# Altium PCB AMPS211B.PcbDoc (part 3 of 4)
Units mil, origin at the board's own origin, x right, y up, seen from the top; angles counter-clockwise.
Board outline 3600 x 2600 mil, 4 copper layers (Top Layer, GND, Power, Bottom Layer), stack 61.6 mil thick; 202 components, 101 nets, 561 pads, 317 vias.
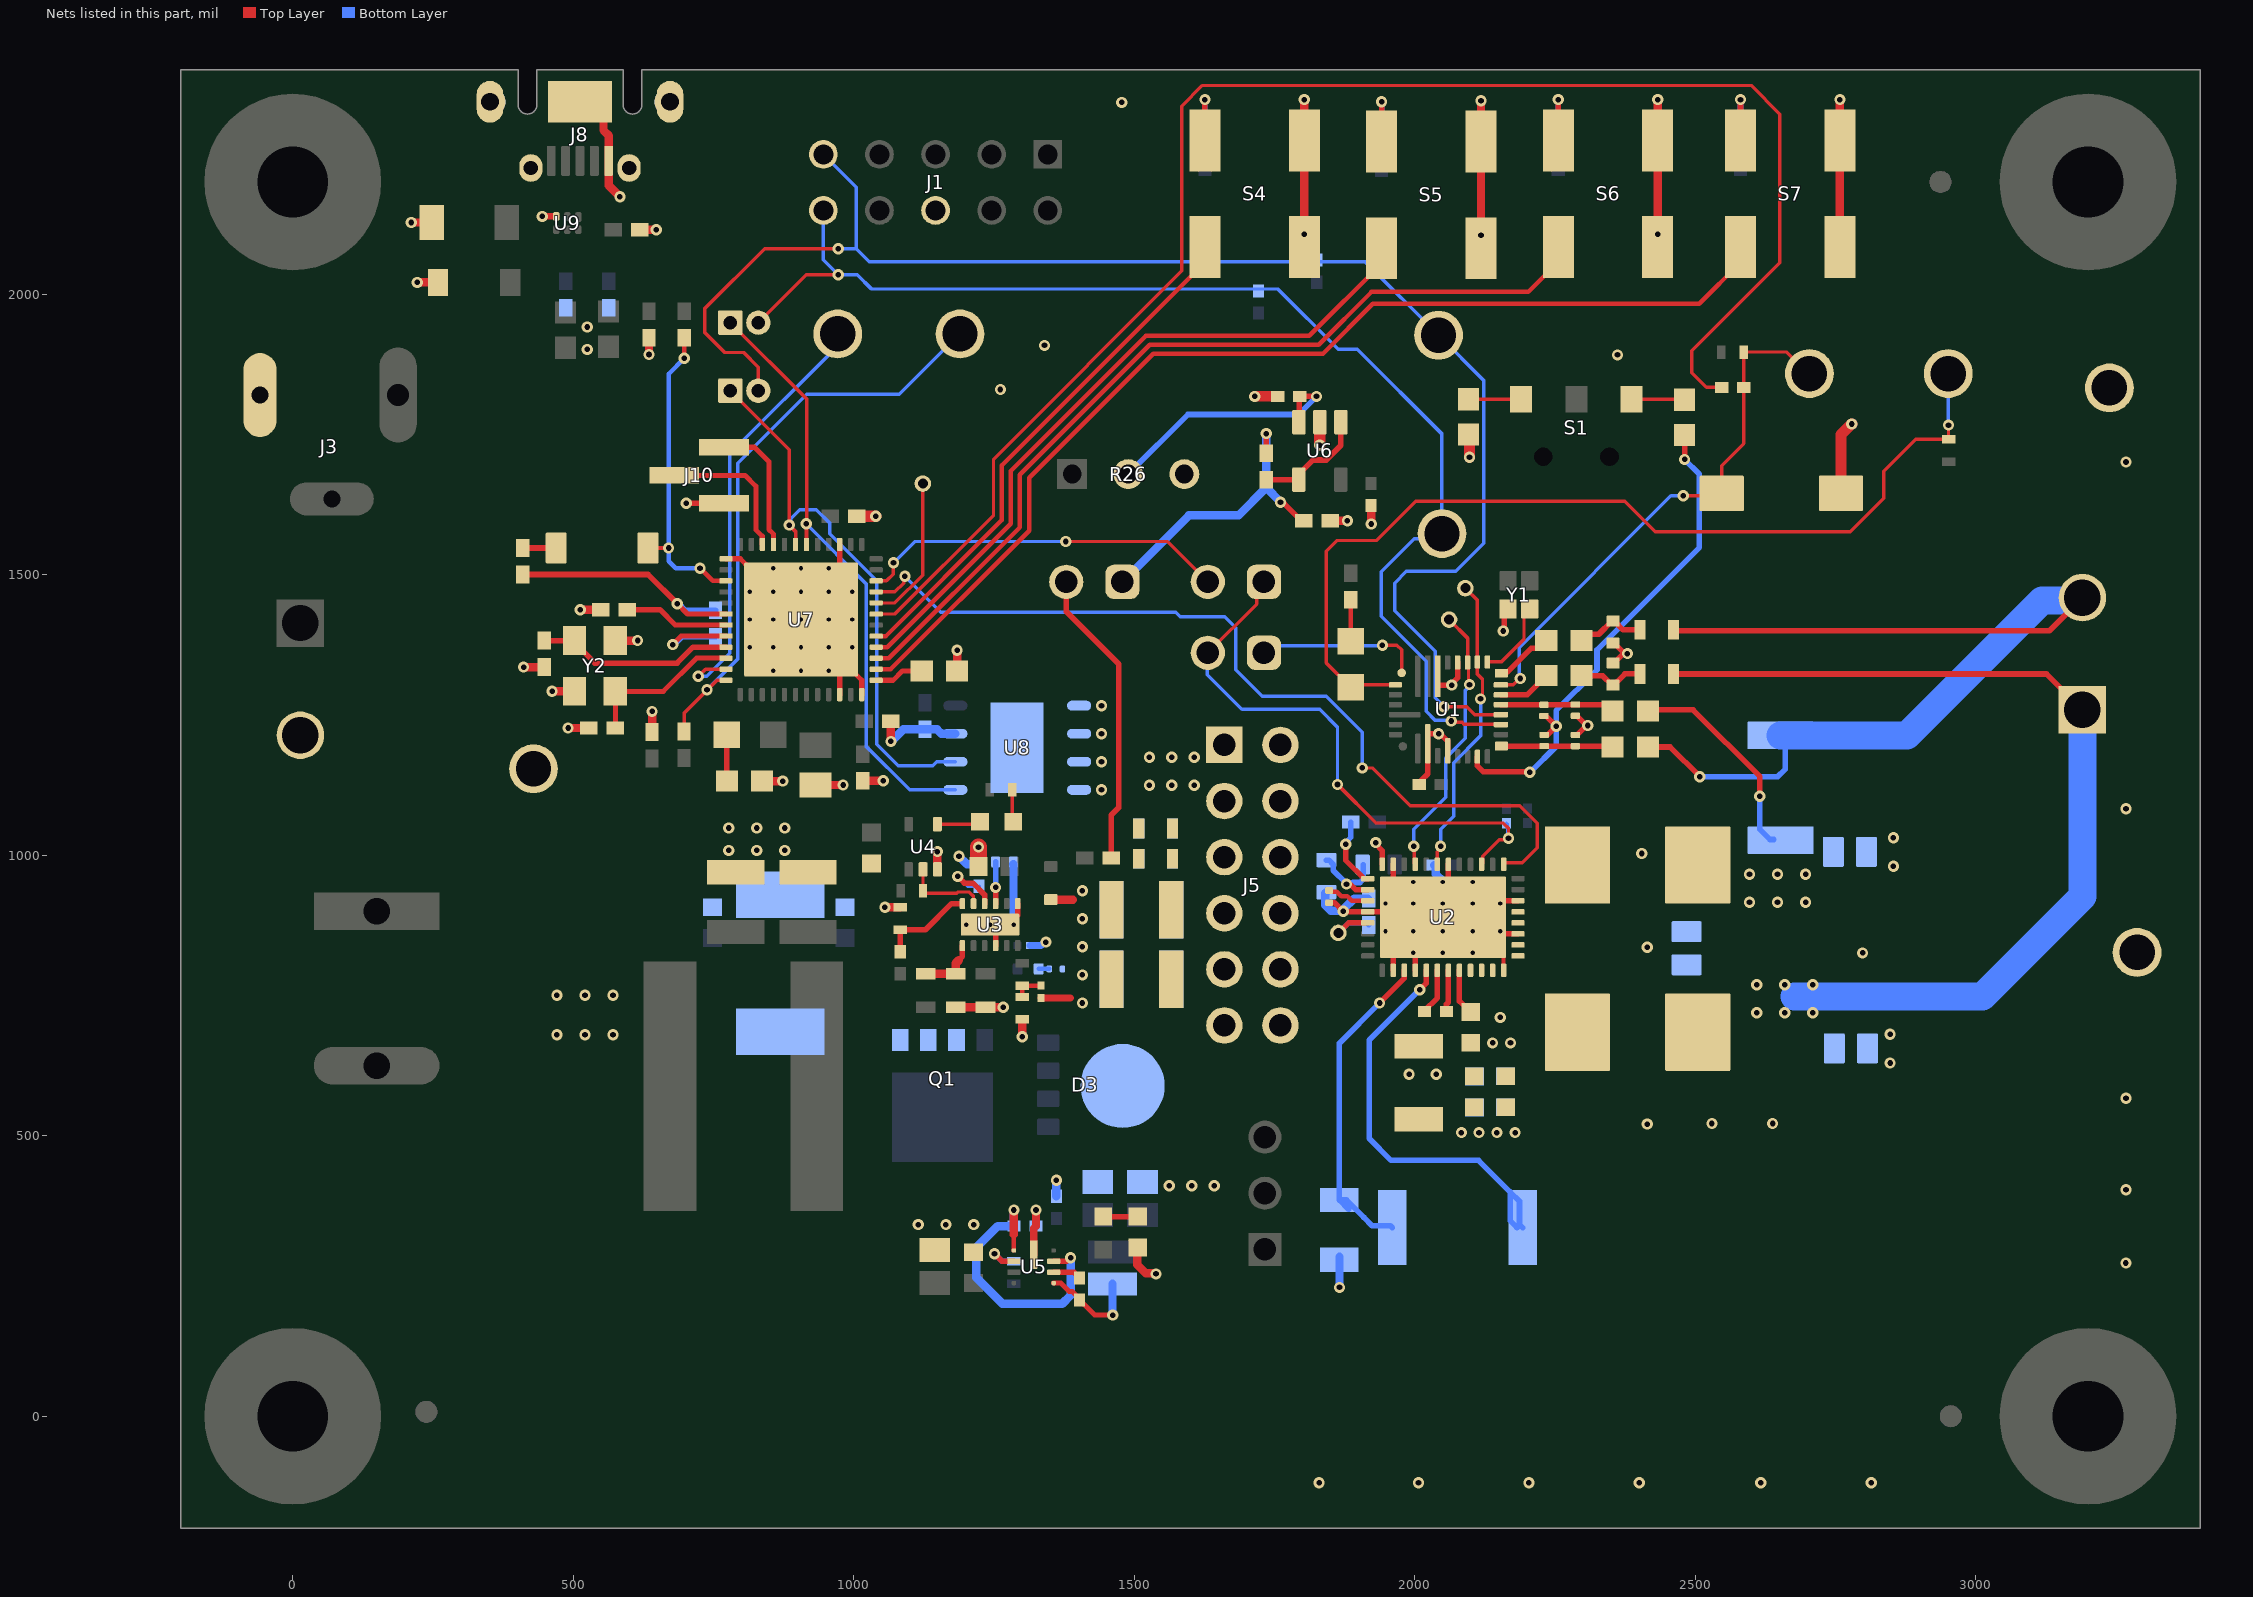
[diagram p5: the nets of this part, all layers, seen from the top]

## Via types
v1: diameter 20, hole 10, Top Layer to Bottom Layer, tented both sides, 277 vias
v2: diameter 19.68, hole 7.87, Top Layer to Bottom Layer, 24 vias
v3: diameter 19.68, hole 7.87, Top Layer to Bottom Layer, tented both sides, 16 vias

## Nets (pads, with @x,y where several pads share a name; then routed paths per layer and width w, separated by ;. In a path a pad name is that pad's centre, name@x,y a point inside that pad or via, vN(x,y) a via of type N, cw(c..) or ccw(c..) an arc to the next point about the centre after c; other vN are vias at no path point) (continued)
GND: C1.2 C3.2 C4.2 C5.2 C7.2 C8.2 C37.2 C38.2 C39.2 C40.1 C41.1 C42.2 C43.2 C44.2 C45.2 C46.2 C47.2 C48.2 C49.2 C50.2 C51.2 C52.2 C53.2 C54.2 C55.2 C56.1 D5.2 J1.6 J5.2 J5.4 J5.6 J8.5 J8.6 J8.7 J8.8 J8.9 J8.10 J10.3 R7.1 R10.1 R15.1 R19.1 R25.1 R42.1 R52.1 R54.1 R57.1 S2.1 S4.3 S4.4 S5.3 S5.4 S6.3 S6.4 S7.3 S7.4 TP2.1 TP3.1 U1.12 U1.14 U1.26 U1.28 U2.2 U2.4 U2.12 U2.15 U2.18 U2.26 U2.31 U2.32 U2.36 U2.41 U7.10 U7.12 U7.27 U7.37 U7.44 U7.49 U8.1 U8.2 U8.3 U8.4 U8.7 U8.9 U9.3 Y1.2 Y2.2 Y2.4 | length 3877.4
  Top Layer w7.5: U2.12@2158.32,794.78 U2.41@2158.32,824.5
  Top Layer w8: U2.41@2147.87,834.95 U2.41@2158.32,824.5
  Top Layer w9.4: v1(677.31,1375.29) 692.5,1390.51 U7.44@772.13,1390.51 ; U7.37@772.13,1528.31 797.74,1528.29 814.45,1511.58 v2(814.45,1469.65) ; v2(905.99,1420.04) v2(955.59,1370.44) 1014.25,1311.77 U7.12@1014.25,1286.18 ; v2(955.59,1328.51) 969.94,1328.51 974.88,1323.56 U7.10@974.88,1286.18 ; v2(955.59,1511.58) 969.94,1511.58 974.88,1516.52 U7.27@974.88,1553.9
  Top Layer w9.5: v1(1930.42,1022.45) 1930.42,1019.61 1941.77,1008.26 U2.32@1941.77,983.88 ; U2.2@1961.47,794.78 U2.41@1961.47,828.56 ; U2.41@1961.47,951 U2.31@1961.47,983.76 ; U2.4@2000.84,794.78 U2.41@2000.84,828.56 ; U2.41@2059.89,949.98 U2.26@2059.89,983.76 ; U2.41@2150.13,859.74 U2.15@2183.91,859.74 ; U2.41@2150.13,918.79 U2.18@2183.91,918.79
  Top Layer w9.8: v1(701.39,1627.37) 768.56,1627.37 J10.3@768.79,1627.14 ; R57.1@1847.24,915.35 1856.64,915.35 1871.96,900.04 v1(1872.34,900.04) 1873.25,899.13 U2.36@1916.17,899.13 ; U2.36@1916.19,899.11 2040.21,899.11 U2.41@2050.05,889.27 ; C5.2@2011.81,1133.86 2023.06,1145.11 U1.26@2023.08,1198.44 ; U1.26@2023.08,1198.44 2023.08,1216.51 2041.34,1216.54 2043.29,1214.58 2047.69,1214.58 2058.51,1203.76 U1.28@2058.51,1186.04 ; U1.14@2040.77,1303.68 2040.77,1303.19 2040.82,1303.15 v1(2065.94,1303.15) 2065.94,1305.74 2076.23,1316.03 U1.12@2076.23,1343.52 ; v1(2157.48,1399.61) 2159.43,1401.56 2159.43,1436.01 Y1.2@2160.43,1437.01 ; R15.1@2286.33,1214.4 2289.28,1214.4 2306.17,1231.3 v1@2306.37,1231.3 ; R10.1@2286.33,1248.39 2289.28,1248.39 v1@2306.37,1231.3 ; v1@2309.06,1231.3 v1@2306.37,1231.3 ; R25.1@2353.35,1342.52 2355.32,1342.52 v1@2372.05,1359.25 ; R19.1@2353.35,1377.95 2355.32,1377.95 2374.02,1359.25 v1(2378.94,1359.25)
  Top Layer w11.8: v1(444.78,2138.53) U9.3@469.68,2138.53
  Top Layer w15: v1(211.17,2127.7) C44.2@247.84,2127.7 ; v1(222.1,2020.98) D5.2@258.76,2020.98 ; v1(411.43,1335.32) C40.1@448.24,1335.32 ; v1(462.28,1292.02) Y2.4@502.09,1292.02 ; v1(490.87,1226.63) C41.1@527.68,1226.63 ; J8.9@512.01,2342.91 523.99,2342.91 553.89,2313.01 553.89,2291.8 563.19,2282.5 J8.5@563.19,2237.6 563.19,2193.62 v1(583.16,2173.65) ; v1(512.33,1437.6) C47.2@549.14,1437.6 ; Y2.2@574.92,1382.57 v1(614.73,1382.57) ; C46.2@618.29,2114.91 v1(647.95,2114.91) ; v1(635.04,1892.38) R52.1@635.04,1922.05 ; C50.2@640.51,1219.55 v1(640.51,1256.36) ; R54.1@836.69,1132 v1(873.5,1132) ; C51.2@932.17,1125.15 v1(980.98,1125.15) ; C53.2@1015.85,1132.87 v1(1052.67,1132.87) ; v1(1066.1,1202.85) C54.2@1066.1,1238.83 C54.2@1066.1,1239.67 ; C48.2@1184.15,1328.51 v1(1184.15,1365.32) ; S4.4@1803.02,2083.96 S4.3@1803.02,2273.92 v1(1803.02,2346.8) ; S5.4@2117.98,2081.99 S5.3@2117.98,2271.95 v1(2117.98,2344.83) ; S6.4@2432.94,2083.96 S6.3@2432.94,2273.92 v1(2432.94,2346.8) ; S7.4@2757.74,2083.96 S7.3@2757.74,2273.92 v1(2757.74,2346.8)
  Top Layer w20: C52.2@1005.36,1604.29 v1(1039.17,1604.29) ; v1(2097.56,1709.1) R7.1@2097.56,1746.78 ; S2.1@2759.62,1644.88 2759.62,1749.49 v1(2778.71,1768.58)
  Bottom Layer w9.8: v1(677.31,1375.29) 680.07,1375.29 693.83,1389.05 C49.2@753.58,1389.05
  Bottom Layer w15: v1@1066.74,1202.85 1088.44,1224.55 C45.2@1126.9,1224.55 ; C45.2@1132.31,1224.14 1148.46,1224.14 1156.11,1216.49 U8.7@1181.13,1216.49 ; R42.1@1842.33,934.15 1840.3,932.13 1840.3,911.09 1850.41,900.99 1871.39,900.99 v1(1872.34,900.04) ; v1(1865.74,229.64) C8.2@1865.74,284.45 ; v1@1872.34,903.04 1892.04,922.73 C7.2@1916.07,922.73 ; C1.2@2034.45,982.28 2035.25,982.28 2037.13,980.4 2037.13,966.44 2050.05,953.53 v3(2050.05,952.26)
  other v1: 1829.33,-118.78 2006.49,-118.78 2203.34,-118.78 2400.19,-118.78 2616.73,-118.78 2813.58,-118.78 3267.46,273.08 3267.67,403.53 2082.98,505.53 2114.43,505.53 2146.36,505.53 2178.67,505.53 2414.28,520.76 2529.53,521.65 2637.8,521.65 3267.72,566.93 2847.12,629.5 2847.12,680.96 2798.14,825.87 2414.28,835.72 2853,980.21 2404.44,1003.04 2853,1031.01 3267.72,1082.68 1441.6,1116.49 1441.6,1166.49 1441.6,1216.49 2042.32,1216.54 2308.33,1231.25 1441.6,1266.49 3267.72,1700.79 1261.28,1829.97 2361.22,1891.73 524.8,1901.45 1340.02,1908.71 524.8,1941.45 2117.98,2104.67 1803.02,2106.64 2432.94,2106.64 1477.81,2341.78
  other v2: 856.38,1328.51 905.99,1328.51 814.45,1370.44 856.38,1370.44 905.99,1370.44 997.52,1370.44 814.45,1420.04 856.38,1420.04 955.59,1420.04 997.52,1420.04 856.38,1469.65 905.99,1469.65 955.59,1469.65 997.52,1469.65 856.38,1511.58 905.99,1511.58
  other v3: 1996.9,826.27 2050.05,826.27 2103.2,826.27 1947.69,864.66 1996.9,864.66 2050.05,864.66 2103.2,864.66 2152.41,864.66 1947.69,913.87 1996.9,913.87 2050.05,913.87 2103.2,913.87 2152.41,913.87 1996.9,952.26 2103.2,952.26
INCLK: U1.9 Y1.3 | length 132.4
  Top Layer w6.2: U1.9@2129.38,1344.51 2154.54,1344.51 2194.63,1384.59 2194.63,1434.79 Y1.3@2194.88,1435.04
IRQZ: D2.2 R21.2 TP12.1 U1.18 | length 1723.1
  Top Layer w6: U1.18@1965.4,1303.64 1890.3,1303.64 D2.2@1885.73,1299.07 1842.26,1342.54 1842.26,1541.54 1861.68,1560.95 1931.83,1560.95 2001.89,1631.01 2374.39,1631.01 2428.82,1576.58 2776.46,1576.58 2835.99,1636.12 2835.99,1684.45 2892.65,1741.11 R21.2@2951.35,1741.11 v1(2951.35,1766.61)
  Bottom Layer w6: TP12.1@2950.7,1855.47 2950.7,1765.96 v1(2951.35,1766.61)
ISNS_N: R8.1 R9.1 R10.2 U1.5 | length 209.5
  Top Layer w9.8: U1.5@2153.39,1268.21 R8.1@2230.11,1268.21 2255.7,1268.21 ; 2255.83,1268.34 2286.33,1268.34 2315.72,1268.34 ; 2315.98,1268.34 R9.1@2363.33,1268.34
ISNS_P: R13.1 R14.1 R15.2 U1.1 | length 208.9
  Top Layer w9.8: U1.1@2154.41,1194.36 2256.25,1194.36 ; 2256.27,1194.34 2315.84,1194.34 ; 2315.92,1194.4 R14.1@2363.39,1194.4
MSP430_SDZ: R22.2 U7.19 | length 2842.8
  Top Layer w6: U7.19@1039.84,1429.88 1073.23,1429.88 1249.14,1605.79 1249.14,1706 1584.52,2041.38 1584.52,2334.98 1621.54,2372 2599.38,2372 2650.7,2320.68 2650.7,2056.05 2493.81,1899.15 2493.81,1859.91 2519.85,1833.86 R22.2@2547.03,1833.86
NetC2_2: C2.2 U2.8 | length 83.1
  Top Layer w9.8: U2.8@2079.58,794.78 2079.58,739.7 2098.72,720.55 C2.2@2099.7,720.55
NetC6_1: C6.1 U2.6 | length 82.5
  Top Layer w9.4: C6.1@2016.69,721.97 2040.21,745.49 U2.6@2040.21,794.78
NetC6_2: C6.2 U2.7 | length 74.5
  Top Layer w9.8: C6.2@2056.16,721.87 2056.16,734.01 2059.89,737.74 U2.7@2059.89,794.78
NetC8_1: C8.1 R5.2 U2.3 | length 595.7
  Top Layer w9.8: v1(1937.16,736.61) 1981.07,780.52 U2.3@1981.07,794.7
  Bottom Layer w10: C8.1@1882.08,368.8 C8.1@1865.43,385.45 ; v1(1937.16,736.61) 1865.43,664.88 C8.1@1865.43,385.45 ; R5.2@1959.85,336.27 1956.65,339.47 1923.88,339.47 1909.38,353.97 1909.38,354.3 1878.22,385.45 C8.1@1865.43,385.45
NetC11_1: C11.1 U5.6 | length 50.5
  Top Layer w9.84: U5.6@1356.24,256.55 1392.58,256.55 C11.1@1402.58,246.55
NetC11_2: C11.2 L4.1 U5.5 | length 186.3
  Top Layer w9: U5.5@1356.24,237.34 1368.92,237.34 1383.89,222.37 1389.37,222.37 1402.58,209.15 C11.2@1402.58,207.18 1402.58,205.21 1407.93,199.87 1409.89,199.87 1429.47,180.3 v1(1461.5,180.3)
  Bottom Layer w15: v1@1461.11,180.69 L4.1@1461.11,235.75
NetC14_1: C14.1 C56.2 L2.2 R4.1 R9.2 | length 373.8
  Top Layer w10: R9.2@2417,1259 2496,1259 2615.09,1139.91 2615.09,1105.09 v1(2615,1105)
  Bottom Layer w10: v1(2615,1105) 2615,1046.1 2633.1,1028 R4.1@2640,1028
  other v1: 2596.48,916.03 2646.48,916.03 2696.48,916.03 2596.48,966.03 2646.48,966.03 2696.48,966.03
NetC16_1: C16.1 U5.1 U5.7 | length 530.5
  Top Layer w7.8: U5.1@1285.37,295.45 1285.37,323.97
  Top Layer w9: U5.7@1356.24,276.24 1380.38,276.24 v1(1386.42,282.27)
  Top Layer w15: 1285.37,323.97 v1(1285.37,367.6)
  Bottom Layer w15: v1(1285.37,367.6) C16.1@1285.37,338.76 1256.59,338.76 1218.33,300.49 1218.33,247.08 1264.95,200.46 1371.6,200.46 1386.42,215.28 v1(1386.42,282.27)
NetC18_1: C18.1 R26.2 U6.3 | length 467.6
  Top Layer w10: U6.3@1793.27,1771.77 1794.16,1772.66 1794.16,1816.88 C18.1@1795.04,1817.76 ; C18.1@1797.01,1817.76 v1(1824.85,1817.76)
  Bottom Layer w10: R26.2@1489.23,1679.28 1595.46,1785.51 1792.6,1785.51 v1(1824.85,1817.76)
NetC22_1: C22.1 R30.1 U3.1 | length 108.4
  Top Layer w9.8: 1187.02,812.71 1193.72,819.42 U3.1@1193.72,838.83
  Top Layer w15: R30.1@1128.28,788.83 C22.1@1181.72,788.83 1181.72,807.42 1187.02,812.71
NetC32_1: C32.1 R33.2 R34.1 | length 53.4
  Top Layer w8: R34.1@1300.46,747.29 R33.2@1300.46,767.33 C32.1@1333.79,767.33
NetC33_1: C33.1 R40.2 | length 18.8
  Bottom Layer w8: C33.1@1329.55,797.23 R40.2@1348.36,797.23
NetC36_1: C36.1 J11.1 R44.1 | length 549
  Top Layer w10: R44.1@1735.22,1716.65 v1(1735.22,1751.46) ; v1(1760.52,1628.94) 1762.43,1627.02 1766.84,1627.02 1797.91,1595.96 C36.1@1801.85,1595.96
  Bottom Layer w15: J11.1@1478.74,1487.2 1597.33,1605.79 1685.91,1605.79 1735.22,1655.11 ; v1(1735.22,1751.46) 1735.22,1655.11 ; v1@1760.83,1628.94 1760.83,1629.5 1735.22,1655.11
NetC40_2: C40.2 U7.45 Y2.3 | length 352.5
  Top Layer w9.4: 731.93,1370.83 U7.45@772.13,1370.83
  Top Layer w9.8: C40.2@448.24,1382.57 498.04,1382.57 538.45,1342.16 685.14,1342.16 713.81,1370.83 731.93,1370.83
NetC41_2: C41.2 U7.46 Y2.1 | length 287.1
  Top Layer w9: C41.2@574.92,1226.63 Y2.1@574.92,1292.02 660.49,1292.02 719.62,1351.14 U7.46@772.13,1351.14
NetC47_1: C47.1 U7.43 | length 187.1
  Top Layer w9.4: C47.1@596.38,1437.6 654.31,1437.6 681.71,1410.2 U7.43@772.13,1410.2
NetC48_1: C48.1 U7.13 | length 83.2
  Top Layer w9: U7.13@1039.84,1311.77 1070.11,1311.77 1086.84,1328.51 C48.1@1116.16,1328.51
NetD1_2: D1.2 R11.2 | length 61.3
  Top Layer w9.84: D1.2@1444.91,355.96 R11.2@1506.16,355.96
NetD2_1: D2.1 R27.2 | length 73.5
  Top Layer w8: D2.1@1885.73,1381.75 R27.2@1885.73,1455.23
NetD4_1: D4.1 R36.2 | length 55.2
  Top Layer w6: D4.1@1282.15,1061.4 R36.2@1282.15,1116.55
NetD4_2: D4.2 U4.4 | length 77.7
  Top Layer w6: U4.4@1149.02,1055.36 1221.01,1055.36 D4.2@1225.07,1059.42
NetD6_2: D6.2 R54.2 | length 82.7
  Top Layer w10: R54.2@773.69,1132 D6.2@773.69,1214.68
NetJ10_1: J10.1 U7.33 | length 241.5
  Top Layer w9: J10.1@768.79,1727.14 823.03,1727.14 848.57,1701.59 848.57,1580.7 856.55,1572.72 856.55,1554.12 U7.33@856.77,1553.9
NetJ10_2: J10.2 U7.34 | length 262
  Top Layer w9: J10.2@680.21,1677.14 799.09,1677.14 806.08,1677.14 825.46,1657.76 825.46,1579.95 836.86,1568.55 836.86,1554.12 U7.34@837.09,1553.9
NetJ11_2: J11.2 R28.2 | length 536.7
  Top Layer w10: J11.2@1378.94,1487.2 1378.74,1487.01 1378.74,1434.12 1472.31,1340.55 1472.31,1084.75 1458.69,1071.13 R28.2@1458.69,995.01
NetR5_1: R5.1 U2.5 | length 774
  Top Layer w9.4: v1@2008.88,760.3 2020.52,771.94 U2.5@2020.52,794.78
  Bottom Layer w10: v1(2008.75,760.3) 1918.69,670.24 1918.69,495.08 1957.85,455.92 2113.82,455.92 R5.1@2169.83,399.92 ; R5.1@2182.13,336.27 2169.83,348.58 R5.1@2169.83,399.92 ; R5.1@2192.13,336.27 2186.62,341.79 2186.62,383.12 R5.1@2169.83,399.92
NetR6_2: R6.2 S1.3 | length 95
  Top Layer w6: S1.3@2386.33,1812.73 2479.98,1812.73 R6.2@2480.93,1811.78
NetR7_2: R7.2 S1.1 | length 93.9
  Top Layer w6: R7.2@2095.56,1812.73 S1.1@2189.48,1812.73
NetR17_2: R17.2 R18.1 R19.2 | length 123.1
  Top Layer w10: R17.2@2296.26,1382.87 R17.2@2297.24,1382.87 R17.2@2309.55,1395.18 ; R17.2@2311.02,1393.7 2327.76,1393.7 R19.2@2351.38,1417.32 ; R19.2@2356,1416 2356.64,1416 2371.06,1401.57 R18.1@2404.56,1401.57
NetR23_2: R23.2 R24.1 R25.2 | length 115.2
  Top Layer w10: R23.2@2297.24,1319.88 2334.65,1319.88 R25.2@2350.39,1304.13 ; R25.2@2354.33,1303.15 2355.31,1303.15 2360.16,1307.99 2360.16,1308.98 2374.45,1323.26 R24.1@2400.94,1323.26
NetR44_2: R44.2 U6.1 U6.4 | length 205.2
  Top Layer w10: R44.2@1735.22,1669.41 U6.4@1793.27,1669.41 1793.27,1679.25 1818.51,1704.49 1842.06,1704.49 1868.07,1730.5 U6.1@1868.07,1771.77
NetR45_1: R45.1 S4.1 | length 145.8
  Top Layer w10: S4.1@1625.85,2273.92 v1(1625.85,2346.8)
  Bottom Layer w10: R45.1@1625.85,2273.92 v1(1625.85,2346.8)
NetR46_1: R46.1 S5.1 | length 145.8
  Top Layer w10: S5.1@1940.82,2269.98 v1(1940.82,2342.86)
  Bottom Layer w10: R46.1@1940.82,2269.98 v1(1940.82,2342.86)
NetR47_1: R47.1 S6.1 | length 145.8
  Top Layer w10: S6.1@2255.78,2273.92 v1(2255.78,2346.8)
  Bottom Layer w10: R47.1@2255.78,2273.92 v1(2255.78,2346.8)
NetR48_1: R48.1 S7.1 | length 145.8
  Top Layer w10: S7.1@2580.58,2273.92 v1(2580.58,2346.8)
  Bottom Layer w10: R48.1@2580.58,2273.92 v1(2580.58,2346.8)
NetR53_1: R53.1 S8.2 | length 58.7
  Top Layer w10: R53.1@409.96,1547.53 S8.2@468.62,1547.53
NetS4_2: S4.2 U7.17 | length 946.2
  Top Layer w8: U7.17@1039.94,1390.61 1057.31,1390.61 1264.02,1597.32 1264.02,1694.66 1625.85,2056.5 S4.2@1625.85,2083.96
NetS5_2: S5.2 U7.16 | length 1266.7
  Top Layer w8: U7.16@1039.84,1370.83 1059.94,1370.79 1279.89,1590.74 1279.89,1684.78 1520.77,1925.66 1811.94,1925.66 1940.82,2054.53 S5.2@1940.82,2081.99
NetS6_2: S6.2 U7.15 | length 1590.6
  Top Layer w8: U7.15@1039.98,1351 1062.6,1351 1295.76,1584.17 1295.76,1678.21 1527.34,1909.78 1828.61,1909.78 1922.71,2003.89 2202.2,2003.89 2231.25,2032.94 2232.22,2032.94 2255.78,2056.5 S6.2@2255.78,2083.96
NetS7_2: S7.2 U7.14 | length 1923.6
  Top Layer w8: U7.14@1039.84,1331.46 1065.5,1331.46 1312.57,1578.52 1312.57,1672.56 1533.92,1893.91 1836.35,1893.91 1925.07,1982.63 2506.71,1982.63 2580.58,2056.5 S7.2@2580.58,2083.96
NetTP14_1: TP14.1 U7.20 | length 266.9
  Top Layer w6: U7.20@1039.84,1449.57 1073.3,1449.57 1122.89,1499.16 1122.89,1662.26 TP14.1@1123.03,1662.4
OCP: R57.2 U2.35 | length 76.5
  Top Layer w8: R57.2@1847.24,937 1849.15,935.1 1860.62,935.1 1869.11,926.61 1879.96,926.61 1887.77,918.79 U2.35@1916.19,918.79
OUT_A: L1.1 U2.13 U2.14
OUT_B: L2.1 U2.16 U2.17
OUT_XA: C14.2 C55.1 J2.1 L1.2 R24.2 | length 1676.2
  Top Layer w10: R24.2@2459,1323 3126,1323 J2.1@3190,1259
  Bottom Layer w50: 2677.17,748.03 3011.81,748.03 3190.02,926.24 3190.02,1253.98 J2.1@3187,1257
  other v1: 2609.28,719.16 2659.28,719.16 2709.28,719.16 2609.28,769.16 2659.28,769.16 2709.28,769.16
OUT_XB: J2.2 R4.2 R14.2 R18.2 | length 1711.4
  Top Layer w10: R14.2@2415.35,1192.91 2455.09,1192.91 v1(2508,1140) ; R18.2@2457,1400 3131,1400 J2.2@3190,1459
  Bottom Layer w10: v1(2508,1140) 2647,1140 2660,1153 R4.2@2660,1193.9
  Bottom Layer w50: R4.2@2652,1213.5 2877.5,1213.5 3118,1454 3185,1454 J2.2@3190,1459 J2.2@3191,1460
OUTOFF-MSP: U2.21 U7.21 | length 1571.9
  Top Layer w6: U7.21@1039.84,1469.25 1073.36,1469.25 1088.74,1484.63 v1@1088.74,1494.69 ; v1(1906.5,1155.51) 1924.21,1155.51 1991.72,1088 2187,1088 2218,1057 2218,1013 2191.22,986.22 2160.24,986.22 2158.32,984.3 U2.21@2158.32,983.76
  Bottom Layer w6: v1(1091.15,1497.1) 1091.25,1497.1 1155.28,1433.07 1573.71,1433.07 1581.58,1425.2 1661.42,1425.2 1681.1,1405.51 1681.1,1330.71 1728.35,1283.46 1842.52,1283.46 1906.5,1219.49 v1(1906.5,1155.51)
PGND: C9.2 C10.2 C12.2 C13.2 C15.2 C16.2 C17.2 C18.2 C19.2 C20.2 C21.2 C22.2 C23.2 C24.2 C25.2 C26.2 C27.2 C28.2 C29.2 C30.2 C31.2 C32.2 C34.2 C35.2 C36.2 C57.2 C58.2 J3.2 J4.2 J5.1 J5.3 J5.5 R11.1 R26.3 R31.1 R37.1 R38.1 R39.1 R40.1 TP1.1 U3.4 U3.7 U3.13@1242.94,876.23 U4.3 U5.9 U6.2 | length 851.6
  Top Layer w9.8: v2(1242.94,876.23) 1252.78,866.38 U3.4@1252.78,838.83 ; v2(1285.26,876.23) 1285.26,886.07 1292.13,892.94 U3.7@1292.15,913.63
  Top Layer w13: C32.2@1333.79,745.28 1386.21,745.28
  Top Layer w13.5: U5.9@1320.8,288.05 1320.8,334.82 1324.74,338.76 v1(1324.74,367.6)
  Top Layer w15: v1(1055.55,907.05) R31.1@1082.84,907.05 ; U4.3@1149.02,974.65 v1(1149.02,1006.45) ; C22.2@1181.72,728.83 C19.2@1234.87,728.83 v1(1266.37,728.83) ; R39.1@1351.2,920.75 1390.71,920.75 ; R11.1@1506.16,300.84 1505.11,299.8 1505.11,270.23 1520.76,254.59 1537.63,254.59 v1(1538.59,253.63) ; C36.2@1849.09,1595.96 v1(1879.9,1595.96) ; v1(1922.19,1590.35) C17.2@1922.19,1621.16
  Top Layer w19: v1(1714.86,1817.76) C18.2@1755.67,1817.76
  Top Layer w20: v1(1830.67,1730.96) U6.2@1830.67,1771.77
  Bottom Layer w12.5: C34.2@1314.2,838.83 C34.2@1314.2,838.83 1334.14,838.87 1340.38,845.12 v1(1342.41,845.12)
  Bottom Layer w15: v1(1187.61,997.97) 1201.8,983.79 R37.1@1223.34,983.79 ; C31.2@1284.27,984.11 1284.65,983.73 1284.65,876.84 v2(1285.26,876.23) ; C16.2@1324.74,338.76 v1(1324.74,367.6) ; C15.2@1361.16,391.9 v1(1361.16,420.75)
  other v1: 1114.87,341.53 1164.27,341.53 1213.67,341.53 1562.38,410.85 1602.38,410.85 1642.38,410.85 1407.48,736.61 1407.48,786.61 1407.48,836.61 1407.48,886.61 1407.48,936.61 777.08,1008.48 827.08,1008.48 877.08,1008.48 777.08,1048.48 827.08,1048.48 877.08,1048.48
  other v2: 1200.61,876.23
PGOOD: R32.2 U3.11 U4.2 | length 147.1
  Top Layer w6: U4.2@1123.43,974.65 R32.2@1123.43,936.27 1127.46,932.24 1183.35,932.24 1185.45,934.34 1205.68,934.34 1213.41,926.62 U3.11@1213.41,913.63
PGOOD3.3: R16.1 U5.2 | length 80.2
  Top Layer w9.84: v1(1250.82,289.58) 1264.17,276.24 U5.2@1285.37,276.24
  Bottom Layer w9.84: v1(1250.82,289.58) 1264.17,276.24 R16.1@1285.37,276.24
PUR: R51.1 S8.1 U7.39 | length 562.4
  Top Layer w8: S8.1@633.97,1547.53 v1(669.92,1547.53) v1@669.99,1547.46 ; v1(698.01,1885.83) R51.1@698.01,1922.05 ; v1@726.17,1511.25 748.48,1488.94 U7.39@772.13,1488.94
  Bottom Layer w8: v1(698.01,1885.83) 669.92,1857.73 v1(669.92,1547.53) 669.92,1523.84 682.51,1511.25 v1(725.96,1511.25)
PVDD: C2.1 C3.1 C4.1 C37.1 C38.1 C39.1 J5.8 J5.10 J5.12 U2.9 U2.10 U2.11
  other v1: 1989.74,609.52 2038.28,609.52 2138.63,665.44 2170.52,665.44 2152.41,710.81
PWMA: TP6.1 U1.10 U2.27 | length 540.5
  Top Layer w6.2: U2.27@2040.21,983.87 2040.21,1006.47 2046,1012.27 v1(2046,1016) ; TP6.1@2090,1477 TP6.1@2090,1476 2111.66,1454.34 U1.10@2111.66,1344.51 2111.66,1322.72 2120.64,1313.74 2120.64,1285.79 2117.13,1282.28 v1(2117.13,1278.54) ; TP6.1@2090,1478 TP6.1@2091,1477
  Bottom Layer w6.2: v1(2046,1016) 2046,1046 2069.19,1069.19 2069.19,1164.66 2117.13,1212.6 v1(2117.13,1278.54)
PWMB: TP7.1 U1.11 U2.29 | length 499.2
  Top Layer w6.2: v1(1998,1016) 1999.42,1014.58 1999.42,985.49 U2.29@2000.93,983.97 ; TP7.1@2057.68,1430.32 TP7.1@2062,1426 ; TP7.1@2061,1419 2062,1419 2093.95,1387.05 U1.11@2093.95,1343.52 2095.69,1341.77 2095.69,1305.88 v1(2097.44,1304.13)
  Bottom Layer w6.2: v1(1998,1016) 1998,1046 2055.12,1103.12 2055.12,1173.23 2090,1208.11 2090,1293.6 2097.44,1301.04 v1(2097.44,1304.13)
RBIAS: R43.1 U2.33 | length 124.7
  Top Layer w9.5: v1(1876.97,1019.69) 1876.97,990.5 1909.3,958.16 U2.33@1916.07,958.16
  Bottom Layer w9.5: v1(1876.97,1019.69) 1876.97,1022.53 1885.83,1031.38 R43.1@1885.83,1059.06
RESETZ: J12.2 J13.1 R12.1 U2.23 | length 1037.1
  Top Layer w6: J12.2@1631.1,1360.63 1718.16,1447.69 1718.16,1474.07 J13.1@1732.28,1488.19 ; v1(1862.2,1125.98) 1930.9,1057.29 2157.71,1057.29 2167,1048 v1(2167,1030) 2164.32,1027.32 2150.32,1027.32 2120.87,997.87 2120.87,985.68 U2.23@2118.95,983.76
  Bottom Layer w6: J12.2@1629.92,1358.27 1629.92,1321.85 1691.93,1259.84 1830.71,1259.84 1862.2,1228.35 v1(1862.2,1125.98) ; R12.1@2163.39,1056.89 2165.19,1055.08 2165.19,1031.81 v1(2167,1030)
RESETZ-MSP: J13.2 U7.22 | length 661.8
  Top Layer w6: U7.22@1039.84,1488.94 1058.3,1488.94 1070.28,1500.92 1070.28,1520.72 v1(1070.87,1521.31) ; v1(1377.95,1559.06) 1559.25,1559.06 1629.92,1488.39 J13.2@1629.92,1488.19
  Bottom Layer w6: v1@1070.87,1519.68 v1(1070.87,1521.31) ; v1(1070.87,1521.31) 1108.62,1559.06 v1(1377.95,1559.06)
RESETZ-ULC: J12.1 U1.17 | length 297.7
  Top Layer w6: v1(1942.2,1374.31) 1968.14,1374.31 1976.6,1365.85 U1.17@1976.6,1324.94
  Bottom Layer w6: J12.1@1728.35,1362.2 1739.74,1373.6 1941.49,1373.6 v1(1942.2,1374.31)
RT: R37.2 U3.10 | length 122.8
  Top Layer w9.8: v1(1185.19,962.21) 1197.29,950.12 1212.44,950.12 1233.07,929.49 U3.10@1233.07,913.65
  Bottom Layer w6: v1(1185.19,962.21) 1202.99,944.42 R37.2@1223.34,944.42
SBWTCK: TP10.1 U7.47 | length 776.2
  Top Layer w6.2: v1@723.19,1318.95 735.7,1331.46 U7.47@772.13,1331.46
  Bottom Layer w6.2: v1(722.83,1318.95) 738.09,1318.95 779.02,1359.88 779.02,1715.3 971.36,1907.63 TP10.1@971.36,1929.13
SBWTDIO: R55.1 TP9.1 U7.48 | length 1048.9
  Top Layer w6.2: R55.1@697.42,1220.58 697.42,1252.84 756.18,1311.6 U7.48@771.95,1311.6
  Bottom Layer w6.2: v1(738.46,1295.01) 793.1,1349.65 793.1,1698.25 916.2,1821.35 1080.76,1821.35 1188.55,1929.13 TP9.1@1189.4,1929.13
SCL: J1.9 J7.2 R1.1 TP4.1 U1.4 | length 2770.1
  Top Layer w6.2: J7.2@829.84,1827.83 829.84,1869.94 803.8,1895.98 770.29,1895.98 734.79,1931.49 734.79,1974.66 841.2,2081.08 v1(972.46,2081.08) ; v1(2052.17,1264.76) 2092.77,1264.76 2107.04,1250.49 U1.4@2153.39,1250.49
  Bottom Layer w6.2: J1.9@945.8,2249.19 1004.28,2190.71 1004.28,2081.08 ; v1(972.46,2081.08) 1004.28,2081.08 ; v1(2052.17,1264.76) 2036.42,1280.51 2036.42,1363.19 1964,1435.61 1964,1485 1984.91,1505.91 2072.83,1505.91 2122.96,1556.03 2122.96,1846.15 TP4.1@2042.31,1926.8 1911.28,2057.83 1027.52,2057.83 1004.28,2081.08
SCL_MSP: J7.1 U7.31 U8.6 | length 1009
  Top Layer w6.2: J7.1@779.84,1827.83 885.02,1722.66 885.02,1588.14 896.14,1577.02 U7.31@896.14,1553.9
  Bottom Layer w6.2: v1(884.79,1588.37) 887.43,1591.01 887.43,1599.57 903.75,1615.89 933.29,1615.89 957.06,1592.12 957.06,1573.01 1041.13,1488.94 1040.69,1488.5 1040.69,1198 1079.2,1159.49 1140.65,1159.49 1147.65,1166.49 U8.6@1181.13,1166.49
SDA: J1.10 J9.2 R2.1 TP5.1 U1.3 | length 2238.3
  Top Layer w6.2: J9.2@829.84,1949.13 915.32,2034.61 v1(972.46,2034.61) v1@974.46,2034.61 ; v1(2064.96,1239.17) 2067.52,1236.61 2084.26,1236.61 2087.36,1233.51 2152.65,1233.51 U1.3@2153.39,1232.77
  Bottom Layer w6.2: J1.10@945.8,2149.19 945.8,2061.28 v1(972.46,2034.61) 1006.24,2034.61 1031.68,2009.18 1755.91,2009.18 1863.51,1901.57 1897.64,1901.57 2048.41,1750.8 TP5.1@2048.41,1573.13 2039.49,1564.2 1999.24,1564.2 1940,1504.96 1940,1425.79 2020.19,1345.6 2020.19,1256.29 2035.9,1240.58 2063.55,1240.58 v1(2064.96,1239.17)
SDA_MSP: J9.1 U7.30 U8.5 | length 1125.9
  Top Layer w6.2: J9.1@779.84,1949.13 915.83,1813.15 U7.30@915.83,1553.9 ; v1@915.6,1590.38 915.6,1548.22 U7.30@915.83,1547.99
  Bottom Layer w6.2: v1(915.37,1590.6) 1022.52,1483.45 1022.52,1193.67 1099.71,1116.49 1140.65,1116.49 U8.5@1181.13,1116.49
SDZ: R20.2 R22.1 S2.2 TP13.1 U1.7 | length 965.5
  Top Layer w6: U1.7@2151.47,1305.56 U1.7@2153.39,1303.64 2175.19,1303.64 2186.55,1315 v1(2188,1315) ; v1(2478.49,1640.59) 2542.73,1640.59 S2.2@2547.03,1644.88 2547.03,1694.38 2586.4,1733.75 R22.1@2586.4,1833.86 R20.2@2586.4,1896.85 2663.31,1896.85 2681.43,1878.73 TP13.1@2703.35,1878.73
  Bottom Layer w6: v1(2188,1315) 2186.02,1316.98 2186.02,1370.08 2456.54,1640.59 v1(2478.49,1640.59)
SLEW: R41.1 R42.2 U2.34 | length 154.1
  Top Layer w9.5: v1@1884.17,948.48 1894.17,938.48 U2.34@1916.07,938.48
  Bottom Layer w10: R42.2@1842.33,991.24 1846.83,991.24 1854.62,983.44 1854.62,972.93 1878.17,949.38 v1(1878.17,948.48) ; v1@1881.17,951.48 1884.17,948.48 1886.88,948.48 1889.75,951.35 1902.21,951.35 1908.07,957.21 R41.1@1908.07,983.27
SOURCE: Q1.1 Q1.2 Q1.3 R34.2 R38.2 | length 31
  Top Layer w15: v1(1300.46,676.29) R34.2@1300.46,707.29
  other v1: 470.87,680.02 520.87,680.02 570.76,680.02 470.87,750.2 520.87,750.2 570.76,750.2
SS: C31.1 U3.9 | length 74.3
  Top Layer w9.8: U3.9@1252.78,913.63 v1(1252.78,942.54)
  Bottom Layer w9.8: v1(1252.78,942.54) C31.1@1252.78,987.91
UVLO: R29.1 R31.2 U3.12 | length 169.2
  Top Layer w9.84: R29.1@1082.84,828 R31.2@1082.84,867.05 1127.65,867.05 1174.23,913.63 U3.12@1193.72,913.63
VBST: C23.1 C24.1 C25.1 C26.1 C27.1 C28.1 C29.1 C30.1 D3.5-6-7-8 J5.7 J5.9 J5.11 R35.2 | length 34.7
  Top Layer w30: R35.2@1222.35,979.81 v1(1222.35,1014.47)
  other v1: 1526.85,1124.61 1566.85,1124.61 1606.85,1124.61 1526.85,1174.61 1566.85,1174.61 1606.85,1174.61
VDD: R6.1 R8.2 R13.2 U1.31 | length 907.6
  Top Layer w9.8: U1.31@2111.68,1175.68 2111.68,1159.26 2121.95,1149 2204,1149 v1(2205,1148) ; R8.2@2230.72,1247.52 2234.64,1247.52 v1@2252.11,1230.05 ; R13.2@2231.27,1215.05 2237.36,1215.05 v1(2252.11,1229.8)
  Top Layer w10: v1(2480.93,1705.43) R6.1@2480.93,1748.79
  Bottom Layer w10: v1(2205,1148) 2206,1148 2252.11,1194.11 2252.11,1229.89 2252,1230 2251.97,1257.74 2324.64,1330.41 2324.64,1366.04 2507.29,1548.7 2507.29,1679.06 v1(2480.93,1705.43)
VREF: C7.1 TP8.1 U2.37 | length 125.1
  Top Layer w9.5: TP8.1@1863.77,861.42 1881.77,879.42 U2.37@1916.07,879.42
  Bottom Layer w9.5: TP8.1@1863.77,861.42 1881.77,879.42 C7.1@1914.13,879.42 ; C7.1@1916.07,879.42 C7.1@1914.13,879.42 ; C7.1@1918.07,875.49 C7.1@1914.13,879.42
VSNS_N: R17.1 U1.8 | length 101.8
  Top Layer w10: U1.8@2155.35,1325.28 2157.25,1327.18 2165.76,1327.18 2207.76,1369.17 2219.57,1369.17 R17.1@2233.27,1382.87
VSNS_P: R23.1 U1.6 | length 95.5
  Top Layer w9.8: U1.6@2153.39,1285.92 2200.29,1285.92 2219.47,1305.1 2219.47,1306.08 2233.27,1319.88 R23.1@2234.25,1319.88
VUSB: C49.1 R53.2 U7.42 | length 464.6
  Top Layer w9.4: v1(685.25,1448.3) 703.67,1429.88 U7.42@772.13,1429.88
  Top Layer w10: R53.2@409.96,1500.29 633.26,1500.29 v1(685.25,1448.3)
  Bottom Layer w10: v1(685.25,1448.3) 687.96,1448.3 699.96,1436.3 C49.1@753.58,1436.3
pads on no net: FID1.1 FID2.1 FID3.1 FID4.1 FID5.1 FID6.1 H1.1 H2.1 H3.1 H4.1 H5.0 H6.0 H7.0 H8.0 J1.1 J1.2 J1.3 J1.4 J1.5 J1.7 J1.8 J3.3 J8.4 LBL1.0 S1.MH1 S1.MH2 SH-J1.0 SH-J2.0 SH-J3.0 SH-J4.0 SH-J5.0 SH-J6.0 SH-J7.0 SH-J8.0 SH-J9.0 U1.15 U1.20 U1.21 U1.22 U1.24 U1.25 U1.29 U2.1 U2.19 U2.20 U2.38 U2.39 U2.40 U3.13@1215.97,876.23 U3.13@1269.9,876.23 U4.1 U7.1 U7.2 U7.3 U7.4 U7.5 U7.6 U7.8 U7.9 U7.18 U7.23 U7.24 U7.25 U7.26 U7.29 U7.32 U7.35 U7.36 U9.4 U9.5

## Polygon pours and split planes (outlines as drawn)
NetC14_1 on Top Layer "TOP_LAYER_NETC14_1_P383" (solid, remove dead copper, pour order 383): 2446,1041 2459,1054 2745,1054 2745,856 2479,856 2446,889 2446,968
3.3V-DRV on Top Layer "TOP_LAYER_3.3V-DRV_P382" (solid, remove dead copper, pour order 382): 2104,974 2104,1002 2133,1031 2133,1044 2131,1046 2086,1046 2075,1035 2075,974
OUT_XA on Top Layer "NONET_L-01_P-001" (solid, remove dead copper, pour order 423): 2745.08,614.17 2447.17,614.17 2428.16,633.19 2428.16,779.3 2438.02,789.17 2745.08,789.17
GND on Top Layer "TOP_LAYER_GND_P440" (solid, remove dead copper, pour order 440): 3389.76,2345.47 3389.76,-153.54 3366.14,-177.17 1784.45,-177.17 1737.2,-129.92 1737.2,1596.46 1538.39,1795.28 1309.05,1795.28 1029.53,1515.75 1029.53,1336.61 959.65,1266.73 465.55,1266.73 354.33,1377.95 354.33,2352.56 381.69,2379.92 3355.31,2379.92
PGND on Top Layer "NONET_L-01_P-001" (solid, remove dead copper, pour order 384): 1092.8,281.66 1099.36,275.1 1229.8,275.1 1233.68,278.98 1233.68,354.19 1229.11,358.76 1096.78,358.76 1092.8,354.78
3.3V-MSP on Top Layer "TOP_LAYER_3.3V-MSP_P385" (solid, remove dead copper, pour order 385): 916.05,1077.32 924.68,1085.95 1101,1085.95 1114.87,1072.09 1114.87,1038.21 1097.33,1020.68 922.49,1020.68 916.05,1027.12
12VIN_SW on Top Layer "NONET_L-01_P-001" (solid, remove dead copper, pour order 387): 1084.47,179.02 1075.51,187.98 1075.51,250.97 1084.37,259.83 1232.08,259.83 1299.22,259.83 1303.15,255.91 1303.15,188.36 1293.81,179.02
PGND on Top Layer "NONET_L-01_P-001" (solid, remove dead copper, pour order 388): 919.02,1007.07 1057.82,1007.07 1062.93,1002.68 1062.93,968.77 1058.99,964.82 1031.58,964.82 1026.59,959.84 1026.59,940.43 1020.16,934.28 741.35,934.28 736.54,939.08 736.54,1058.54 747.88,1069.88 884.69,1069.88 895.69,1058.88 895.69,1030.4
OUT_A on Top Layer "TOP_LAYER_OUT_A_P389" (solid, remove dead copper, pour order 389): 2367.15,635.06 2367.15,603.11 2355.97,591.93 2240.82,591.93 2230.91,601.84 2230.91,768.46 2226.59,772.78 2184.06,772.78 2174.22,782.63 2174.22,841.19 2177.92,844.89 2362.32,844.89 2367.15,840.06
OUT_B on Top Layer "TOP_LAYER_OUT_B_P390" (solid, remove dead copper, pour order 390): 2199.75,903.72 2219,922.97 2219,1064 2245.67,1090.67 2299.77,1090.67 2359.61,1090.67 2367.15,1083.14 2367.15,894.76 2346.69,874.3 2171.76,874.3 2168.94,877.13 2168.94,900.56 2172.09,903.72
PGND on Top Layer "NONET_L-01_P-001" (solid, remove dead copper, pour order 391): 1493.02,710.81 1503.85,721.63 1503.85,959.36 1522.23,978.01 1522.23,1069.88 1515.87,1075.32 1486.29,1075.32 1484.47,1073.5 1484.47,973.38 1479.45,968.36 1403.26,968.36 1380.82,945.92 1380.82,723.99 1394,710.81
3.3V-MSP on Top Layer "NONET_L-01_P-001" (solid, remove dead copper, pour order 392): 1781.51,199.85 1800.56,218.9 1800.56,335.81 1792.84,343.53 1682.22,343.53 1647.86,377.89 1554.42,377.89 1535.07,358.54 1535.07,277.27 1531.62,273.83 1480.63,273.83 1472.31,282.1 1472.31,314.08 1462.72,323.66 1342.63,323.66 1338.13,319.16 1338.13,292.86 1340.11,290.88 1340.2,290.97 1405.16,290.97 1407.48,288.66 1407.48,283.67 1423.03,268.12 1423.03,208.14 1431.32,199.85
DRAIN on Top Layer "NONET_L-01_P-001" (solid, remove dead copper, pour order 394): 864.67,803.07 874.9,813.3 978.97,813.3 983.1,809.16 983.1,751.48 1025.88,708.7 1025.88,280.61 1016.99,271.72 877.48,271.72 864.67,284.52
VBST on Top Layer "NONET_L-01_P-001" (solid, remove dead copper, pour order 395): 1638.46,946.89 1698.35,946.89 1704.22,941.03 1704.22,641.48 1686.03,623.09 1527.6,623.09 1519.53,631.15 1519.53,954.73 1540.27,975.47 1540.27,1080.2 1509.35,1111.12 1509.35,1184.21 1523.56,1198.5 1606.42,1198.5 1618.77,1186.43 1618.77,966.59
12VIN_SW on Top Layer "NONET_L-01_P-001" (solid, remove dead copper, pour order 396): 578.33,519.82 411.83,519.82 260.26,671.39 -10.18,671.39 -40.35,641.22 -40.35,284.55 80.95,163.25 790.15,163.25 818.83,191.93 818.83,802.91 849.56,833.64 980.03,833.64 998.16,815.5 998.16,761.98 1064.07,696.07 1140.47,696.07 1145.69,701.29 1145.69,739.13 1140.92,743.91 1115.05,743.91 1094.43,764.52 1094.43,797.61 1091.55,800.5 1067.91,800.5 1062.72,805.69 1062.72,843.3 996.18,909.84 971.99,909.84 829.52,909.84 663.96,909.84 619.35,865.23 619.35,560.84
12VIN on Top Layer "TOP_LAYER_12VIN_P425" (solid, remove dead copper, pour order 425): -139.12,800.29 261.14,800.29 299.62,838.77 299.62,1884.37 237.32,1946.67 -93.15,1946.67 -150.05,1889.78 -150.05,811.22
PVDD on Top Layer "TOP_LAYER_PVDD_P427" (solid, remove dead copper, pour order 427): 1729.59,938.55 1806.33,938.55 1813.94,930.9 1813.94,772.45 1895.39,691 2123.66,691 2128.39,695.74 2128.39,743.78 2123.74,748.43 2092.05,780.12 2092.05,807.98 2092.09,808.03 2144.84,808.03 2144.84,779.55 2206.72,717.68 2206.72,609.52 2185.64,588.44 1735.81,588.44 1720.84,603.42 1720.84,929.79
GND on Top Layer "NONET_L-01_P-001" (solid, remove dead copper, pour order 428): 1942.09,568.91 1946.17,573 2200.24,573 2205.07,568.16 2205.07,478.3 2198.6,471.84 1947.17,471.84 1942.09,476.92
3.3V-MSP on Top Layer "TOP_LAYER_3.3V-MSP_P429" (solid, remove dead copper, pour order 429): 1014.34,1736.65 1014.34,1649.85 999.07,1634.58 980.9,1634.58 977.08,1630.76 977.08,1588.11 974.98,1586.01 942.83,1586.01 935.62,1593.22 935.62,1745 948.66,1758.04 1000.82,1758.04 1014.34,1744.52
3.3V-MSP on Top Layer "NONET_L-01_P-001" (solid, remove dead copper, pour order 431): 813.32,1257.55 813.32,1168.81 823.25,1158.88 1037.79,1158.88 1040.4,1161.49 1040.4,1256.41 1033.89,1262.92 1010.62,1262.92 1003.56,1269.98 1003.56,1296.68 998.94,1301.31 987.17,1301.31 983.92,1298.06 983.92,1266.94 980.6,1263.63 931.58,1263.63 923.18,1272.03 923.18,1299.71 920.89,1302 907.22,1302 905.95,1300.73 905.95,1271.67 898.48,1264.2 819.98,1264.2
3.3V-MSP on Top Layer "NONET_L-01_P-001" (solid, remove dead copper, pour order 438): 715.91,1108.24 588.49,1108.24 578.77,1117.95 578.77,1183.14 591.68,1196.05 718.64,1196.05 726.76,1187.93 726.76,1119.09
3.3V-MSP on Top Layer "TOP_LAYER_3.3V-MSP_P439" (solid, remove dead copper, pour order 439): 1851.58,1649.38 1857.67,1643.28 1881.03,1643.28 1890.85,1653.1 1954.65,1653.1 1983.7,1682.14 1983.7,1784.02 1975.55,1792.17 1912.12,1792.17 1900.52,1780.57 1900.52,1733.97 1851.58,1685.03
GND on Bottom Layer "BOTTOM_LAYER_GND_P437" (solid, remove dead copper, pour order 437): 3389.76,2345.47 3389.76,-153.54 3366.14,-177.17 1784.45,-177.17 1737.2,-129.92 1737.2,1596.46 1665.35,1668.31 1182.09,1668.31 1029.53,1515.75 1029.53,1336.61 982.28,1289.37 489.17,1289.37 354.33,1424.21 354.33,2195.87 538.38,2379.92 3355.31,2379.92
PGND on Bottom Layer "BOTTOM_LAYER_PGND_P407" (solid, remove dead copper, pour order 407): 883.17,1080.78 894.24,1069.71 894.24,986.16 906.45,973.96 966.99,973.96 1003.94,937.01 1003.94,893.7 998.03,887.8 734.25,887.8 708.95,913.09 708.95,1063.53 726.2,1080.78
12VIN_SW on Bottom Layer "BOTTOM_LAYER_12VIN_SW_P443" (solid, remove dead copper, pour order 443): 685.04,870.08 1000,870.08 1000,822.83 685.04,822.83
PVDD on Bottom Layer "BOTTOM_LAYER_PVDD_P386" (solid, remove dead copper, pour order 386): 1993.13,723.86 2200.54,723.86 2206.72,717.68 2206.72,609.52 2177.99,580.79 1979.2,580.79 1971.54,588.44 1971.54,700.22
PGND on Bottom Layer "BOTTOM_LAYER_PGND_P404" (solid, remove dead copper, pour order 404): 1403.7,438.84 1403.7,396.78 1407.35,392.96 1654.24,392.96 1661.24,399.97 1661.24,437.77 1657.19,441.82 1406.68,441.82
GND on Bottom Layer "BOTTOM_LAYER_GND_P405" (solid, remove dead copper, pour order 405): 1448.56,1280.82 1456.03,1273.35 1456.03,1104.04 1445.74,1093.75 1251.39,1093.75 1232.39,1112.75 1232.39,1273.63 1239.57,1280.82
3.3V-MSP on Bottom Layer "BOTTOM_LAYER_3.3V-MSP_P406" (solid, remove dead copper, pour order 406): 1097.46,857.99 1118.66,857.99 1123.6,862.93 1123.6,1009.31 1141.12,1026.84 1206.16,1026.84 1215.76,1036.43 1215.76,1089.57 1215.93,1089.75 1207.78,1097.89 922.88,1097.89 912.95,1088.45 912.95,1009.85 929.32,993.48 969.5,993.48 998.16,964.82 998.16,863.87 1004.05,857.99
PGND on Bottom Layer "NONET_L-01_P-001" (solid, remove dead copper, pour order 408): 1362.95,732.62 1362.95,946.96 1388.13,972.14 1467.48,972.14 1479.22,983.88 1479.22,1076.47 1482.69,1080.06 1522.06,1080.06 1525.26,1076.87 1525.26,726.47 1520.89,722.11 1373.45,722.11
3.3V-MSP on Bottom Layer "NONET_L-01_P-001" (solid, remove dead copper, pour order 409): 1695.4,344.56 1660.85,379.1 1388.53,379.1 1377.65,368.22 1351.04,368.22 1346.65,363.84 1346.65,318.99 1346.44,318.78 1311.41,318.78 1307.52,314.89 1307.52,258.79 1305.75,257.02 1270.45,257.02 1267.58,254.16 1267.58,224.29 1271.43,220.44 1372.19,220.44 1376.42,224.68 1376.42,265 1377.86,266.43 1381.3,266.43 1637.98,266.43 1770.46,266.43 1776.39,272.37 1776.39,336.27 1768.11,344.56
OUT_XA on Bottom Layer "NONET_L-01_P-001" (solid, remove dead copper, pour order 410): 2442.1,661.07 2442.1,803.1 2465,826 2724.74,826 2765,785.74 2765,662 2736,633 2470.17,633
NetC14_1 on Bottom Layer "NONET_L-01_P-001" (solid, remove dead copper, pour order 411): 2439,981 2439,866 2459,846 2727.03,846 2776,896.02 2776,1058 2516,1058
SOURCE on Bottom Layer "NONET_L-01_P-001" (solid, remove dead copper, pour order 412): 458.17,776.29 446.21,764.33 446.21,649.54 458.86,636.89 967.25,636.89 1195.16,636.89 1202.81,644.54 1202.81,768.89 1195.41,776.29
VBST on Bottom Layer "NONET_L-01_P-001" (solid, remove dead copper, pour order 413): 1505.2,1119.26 1505.2,1191.64 1516.03,1202.46 1612.29,1202.46 1623.26,1191.49 1623.26,969.45 1641.71,950.4 1690.43,950.4 1715.86,924.96 1715.86,581.93 1591.47,457.53 1395.25,457.53 1387,465.78 1387,695.06 1398.34,706.4 1526.55,706.4 1540.49,720.34 1540.49,1083.97
DRAIN on Bottom Layer "NONET_L-01_P-001" (solid, remove dead copper, pour order 414): 904.99,264.78 883.5,286.27 883.5,602.89 896.56,615.95 1278.73,615.95 1281.6,618.81 1281.6,681.04 1285.88,685.32 1368.86,685.32 1371.98,682.2 1371.98,484.27 1252.43,364.72 1091.78,364.72 1080.87,353.8 1080.87,279 1066.65,264.78
GND on Bottom Layer "BOTTOM_LAYER_GND_P415" (solid, remove dead copper, pour order 415): 2787,964 2864.38,964 2871.05,970.67 2871.05,1043.06 2864,1050.11 2787,1050.11
12VIN on Bottom Layer "BOTTOM_LAYER_12VIN_P417" (solid, remove dead copper, pour order 417): -139.12,800.29 261.14,800.29 299.62,838.77 299.62,1884.37 237.32,1946.67 -93.15,1946.67 -150.05,1889.78 -150.05,811.22
GND on Bottom Layer "BOTTOM_LAYER_GND_P418" (solid, remove dead copper, pour order 418): 573.67,1991.66 576.97,1988.36 576.97,1941.16 576.97,1908.24 556.36,1887.63 477.81,1887.63 468.74,1896.7 468.74,1986.9 473.51,1991.66
3.3V-MSP on Bottom Layer "BOTTOM_LAYER_3.3V-MSP_P419" (solid, remove dead copper, pour order 419): 1574.46,2227.9 1574.46,2149.87 1582.01,2142.32 2627.82,2142.32 2634.28,2148.78 2634.28,2228.9 2618.74,2244.44 1591,2244.44
12VIN_SW on Bottom Layer "BOTTOM_LAYER_12VIN_SW_P421" (solid, remove dead copper, pour order 421): -2.86,663.52 -2.86,249.79 69.34,177.59 284.11,177.59 516.99,-55.29 1235.71,-55.29 1257.28,-33.72 1257.28,191.74 1182.15,266.87 1095.93,266.87 1045.45,216.38 925.84,216.38 819.02,323.2 819.02,468.5 721.83,565.7 380.28,565.7 265.96,680.02 13.65,680.02
GND on Bottom Layer "NONET_L-01_P-001" (solid, remove dead copper, pour order 422): 2193.51,572.34 2051.66,572.34 2044.57,565.26 2044.57,484.39 2048.74,480.23 2192.22,480.23 2201.69,489.7 2201.69,564.16
3.3V-MSP on Bottom Layer "NONET_L-01_P-001" (solid, remove dead copper, pour order 424): 1121.89,1389.7 1306.86,1389.7 1329.23,1367.33 1329.23,1299.38 1325.9,1296.05 1232.95,1296.05 1218.33,1281.44 1218.33,1255.08 1214.27,1251.02 1112.61,1251.02 1106.4,1257.23 1106.4,1374.2
GND on Bottom Layer "BOTTOM_LAYER_GND_P433" (solid, remove dead copper, pour order 433): 2788,612.89 2859.41,612.89 2863.84,617.32 2863.84,693.37 2858.09,699.11 2788,699.11
3.3V-MSP on Power "NONET_L-01_P-001" (solid, remove dead copper, pour order 426): 1020.54,1256.97 1038.59,1275.02 1037.36,1276.24 1037.36,1488.8 942.93,1583.24 942.93,2084.66 976.07,2117.8 1637.24,2117.8 1637.24,1256.66 1610.9,1230.31 1495.51,1230.31 1476.73,1211.54 1476.73,1090.66 1462.08,1076 1182.77,1076 1161.42,1051.87 1161.42,984.25 1179.67,966 1497.81,966 1519.9,943.9 1519.9,515.32 1691.87,343.36 1766.63,343.36 1811.66,298.33 1811.66,92.19 1779.33,59.87 1330.1,59.87 1291.35,98.61 1291.35,438.93 1355.32,502.89 1355.32,728.35 1256.16,827.51 -152.12,827.51 -174.99,850.37 -174.99,2339.63 -139.47,2375.15 2831.55,2375.15 2885.32,2321.37 2885.32,1969.83 2864.06,1948.82 2273.62,1948.82 2234.25,1909.45 2234.25,1718.5 2181.1,1665.35 1909.45,1665.35 1866.14,1708.66 1866.14,2035.43 1783.77,2117.8 467.5,2117.8 375.94,2026.24 375.94,1281.65 400.62,1256.97
3.3V-ULC on Power "POWER_3.3V-ULC_P397" (solid, remove dead copper, pour order 397): 2124,1141 2124,1389 2177,1442 2765.84,1442 2893.7,1314.14 2893.7,620.08 2706.62,433 1697.66,433 1684.2,419.54 1684.2,373.53 1698.78,358.95 1797.05,358.95 1852,304 2872.9,304 3080.17,511.27 3080.17,1890.93 3038.3,1932.8 2279.09,1932.8 2255.78,1909.49 2255.78,1644.22 2215.83,1604.28 1908.72,1604.28 1846.46,1666.54 1846.46,2003.94 1783.46,2066.93 1657.48,2066.93 1657.48,1433.07 1982.55,1108 2091,1108
GND on Power "POWER_GND_P442" (solid, remove dead copper, pour order 442): 2322.83,462.6 2696.85,462.6 2864.17,629.92 2864.17,1299.21 2746.06,1417.32 2214.57,1417.32 2155.51,1358.27 2155.51,1171.26 2322.83,1003.94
